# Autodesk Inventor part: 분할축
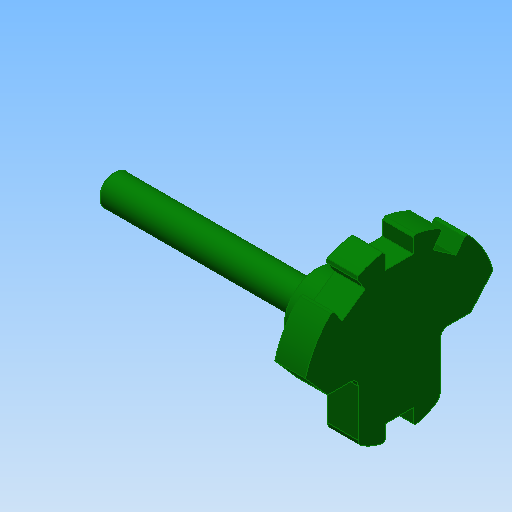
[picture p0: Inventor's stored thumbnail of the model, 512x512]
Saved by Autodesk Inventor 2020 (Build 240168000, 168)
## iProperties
Created: 2016-11
Part Number: 분할축
Material: 강철, 연강
Document SubType Name: Modeling
Designer: mduedu
Density: 7.86 g/cm^3
Appearance: 진녹색
Mass: 410.601 g
Surface Area: 132.471 cm^2
Volume: 52.2393 cm^3
Author: mduedu
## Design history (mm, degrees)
sketch "스케치1"
  geometry: C1 r 38 at (0, 0); 1 further point
  constraints: 1 centre point, 1 coincident
  dimensions: "d0" = 76 diameter of C1
extrude "돌출1" new body sketch "스케치1" distance "d1" = 12; taper "d2" = 0 deg
sketch "스케치2"
  geometry: L1 (0, 38)-(0, -38); L2 (5.5, 37.6)-(5.5, 31); L3 (5.5, 31)-(-5.5, 31); L4 (-5.5, 31)-(-5.5, 37.6); A1 r 38 centre (0, 0) between (0, 38) and (0, -38) reference; A2 r 38 centre (0, 0) between (5.5, 37.6) and (-5.5, 37.6); 2 further points
  constraints: 8 end point, 6 point on circle, 2 coincident, 2 vertical, 1 centre point, 1 horizontal, 1 midpoint, 1 parallel, 1 symmetric about line
  dimensions: "d3" = 11 distance of L2.end L3.end; "d5" = 31 distance from line of L3 point (0, 0)
extrude "돌출2" cut sketch "스케치2" extent not by distance; stored distance "d7" = 12; taper "d8" = 0 deg
sketch "스케치3"
  geometry: L1 (-16, 0)-(-38, 0); L2 (16, 0)-(38, 0); L3 (0, -28)-(0, 28); L4 (-16, -22.978)-(-16, 0); L5 (16, -22.978)-(16, 0); A1 r 38 centre (0, 0) between (-5.5, 37.6) and (-17.061, 33.955) reference; A2 r 38 centre (0, 0) between (-38, 0) and (38, 0); A3 r 28 centre (0, 0) between (-16, -22.978) and (16, -22.978); 4 further points
  constraints: 10 end point, 7 point on circle, 3 coincident, 2 centre point, 2 horizontal alignment, 2 midpoint, 2 parallel, 1 collinear, 1 horizontal, 1 perpendicular, 1 other
  dimensions: "d13" = 32 distance between parallel lines of L5 L4; "d14" = 28 radius of A3
extrude "돌출3" cut sketch "스케치3" extent not by distance; stored distance "d15" = 12; taper "d16" = 0 deg
sketch "스케치4"
  geometry: L1 (0, 0)-(0, -28); L2 (5.5, -27.455)-(5.5, -21); L3 (5.5, -21)-(-5.5, -21); L4 (-5.5, -21)-(-5.5, -27.455); A1 r 28 centre (0, 0) between (-16, -22.978) and (16, -22.978) reference; A2 r 28 centre (0, 0) between (16, -22.978) and (0, -28); A3 r 28 centre (0, 0) between (-5.5, -27.455) and (5.5, -27.455); 1 further point
  constraints: 8 end point, 7 point on circle, 2 centre point, 2 coincident, 1 horizontal, 1 parallel, 1 other
  dimensions: "d17" = 11 distance between parallel lines of L2 L4; "d19" = 21 distance from line of L3 point (0, 0)
extrude "돌출4" cut sketch "스케치4" extent not by distance; stored distance "d20" = 12; taper "d21" = 0 deg
sketch "스케치5"
  geometry: C1 r 13 at (0, 0); 1 further point
  constraints: 1 centre point, 1 coincident
  dimensions: "d22" = 26 diameter of C1
extrude "돌출5" join sketch "스케치5" distance "d23" = 20; taper "d24" = 0 deg
sketch "스케치6"
  geometry: C1 r 6 at (0, 0); 1 further point
  constraints: 1 centre point, 1 coincident
  dimensions: "d25" = 12 diameter of C1
extrude "돌출6" join sketch "스케치6" distance "d26" = 80; taper "d27" = 0 deg
fillet "모깎기1" dims "d28" = 3
chamfer "모따기1" distance "d29" = 1; stored, may be unused: second distance "d30" = 2, angle "d31" = 45 deg
sketch "스케치7"
  geometry: L1 (-20, 13)-(-20, -13) reference; L2 (-20, 6)-(-99, 6) reference; L3 (0, 0)-(-20, 0); C1 r 1 at (-21, 6)
  constraints: 2 end point, 1 centre point, 1 midpoint, 1 tangent
  dimensions: "d32" = 2 diameter of C1; "d33" = 10 dimension on C1 L3
revolve "회전1" sketch "스케치7" stored, may be unused: angle "d34" = 90 deg
chamfer "모따기2" distance "d35" = 1; stored, may be unused: second distance "d36" = 2, angle "d37" = 45 deg
chamfer "모따기3" distance "d38" = 10; stored, may be unused: second distance "d39" = 2, angle "d40" = 45 deg
chamfer "모따기4" distance "d41" = 1; stored, may be unused: second distance "d42" = 2, angle "d43" = 45 deg
fillet "모깎기2" dims "d44" = 3
node "솔리드1"
pattern_circular "원형 패턴1" dims angle "d10" = 35 deg
other parameters: "d12" = 56
